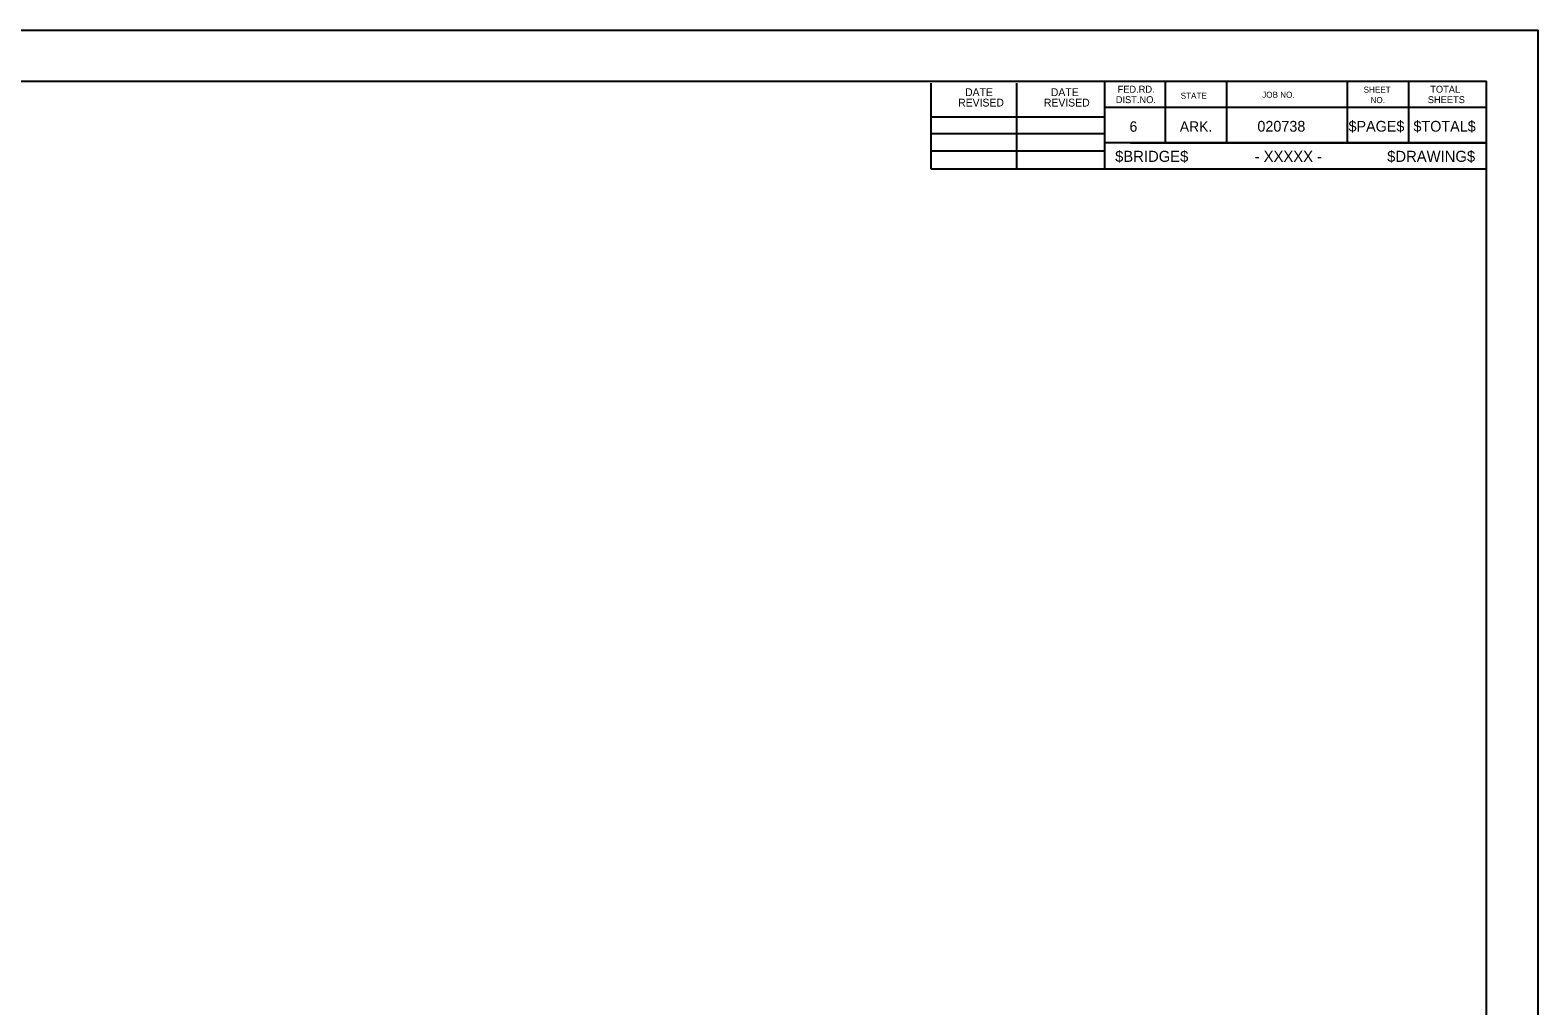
# Model space of a CAD drawing. Extents: x 16 to 1228743, y 11 to 152440.
# Drawn here: x 17.074 to 18.49, y 11.626 to 12.543 of the extents above; entities that cross this region are included whole.
import ezdxf

# ---------------------------------------------------------------- set-up
doc = ezdxf.new("R2010")
doc.units = 0
doc.layers.add('B_Copy In', color=7, linetype='Continuous')
doc.layers.add('R_Border', color=7, linetype='Continuous')

msp = doc.modelspace()

# ---------------------------------------------------------------- linework, layer by layer
at = {"layer": 'R_Border'}
for p, q in [((15.7833, 12.4948), (18.4422, 12.4948)), ((17.9202, 12.4124), (17.9202, 12.4931)), ((18.0009, 12.4124), (18.0009, 12.4931)), ((18.0831, 12.4948), (18.0831, 12.4124)), ((18.1401, 12.4948), (18.1401, 12.4369)), ((18.1979, 12.4948), (18.1979, 12.4369)), ((18.3111, 12.4948), (18.3111, 12.4369)), ((18.3689, 12.4948), (18.3689, 12.4369)), ((18.4422, 10.7576), (18.4422, 12.4948)), ((18.4422, 12.4703), (18.0831, 12.4703)), ((18.4422, 12.4704), (18.4422, 12.4704)), ((17.9202, 12.4613), (18.0831, 12.4613)), ((17.9202, 12.4458), (18.0831, 12.4458)), ((17.9202, 12.4296), (18.0831, 12.4296)), ((18.4422, 12.4369), (18.0831, 12.4369)), ((18.1077, 12.4369), (18.4422, 12.4369)), ((18.4422, 12.4124), (17.9202, 12.4124))]:
    msp.add_line(p, q, dxfattribs=at)
msp.add_lwpolyline([(15.657, 12.5428), (18.4903, 12.5428), (18.4903, 10.7095), (15.657, 10.7095)], close=True, dxfattribs=at)

# ---------------------------------------------------------------- texts
at = {"layer": 'B_Copy In'}
msp.add_text('- XXXXX -', height=0.0104, dxfattribs=at).set_placement((18.2242, 12.4191))
at = {"layer": 'R_Border'}
for s, height, p in [('DATE', 0.00733, (17.9521, 12.4809)), ('DATE', 0.00733, (18.0327, 12.4809)), ('DIST.NO.', 0.00652, (18.0937, 12.4743)), ('FED.RD.', 0.00652, (18.0954, 12.4841)), ('STATE', 0.0057, (18.1547, 12.4784)), ('JOB NO.', 0.0057, (18.2313, 12.4793)), ('SHEET', 0.0057, (18.3266, 12.4841)), ('SHEETS', 0.00652, (18.3869, 12.4743)), ('TOTAL', 0.00652, (18.3892, 12.4841)), ('REVISED', 0.00733, (17.9456, 12.4711)), ('REVISED', 0.00733, (18.0262, 12.4711)), ('NO.', 0.0057, (18.3331, 12.4743)), ('6', 0.00977, (18.1067, 12.4474)), ('ARK.', 0.00977, (18.1539, 12.4474)), ('020738', 0.01009, (18.2268, 12.4475)), ('$PAGE$', 0.01009, (18.3124, 12.4475)), ('$TOTAL$', 0.01009, (18.3734, 12.4475)), ('$BRIDGE$', 0.0104, (18.0931, 12.4191)), ('$DRAWING$', 0.0104, (18.3487, 12.4191))]:
    msp.add_text(s, height=height, dxfattribs=at).set_placement(p)

doc.saveas('drawing.dxf')
